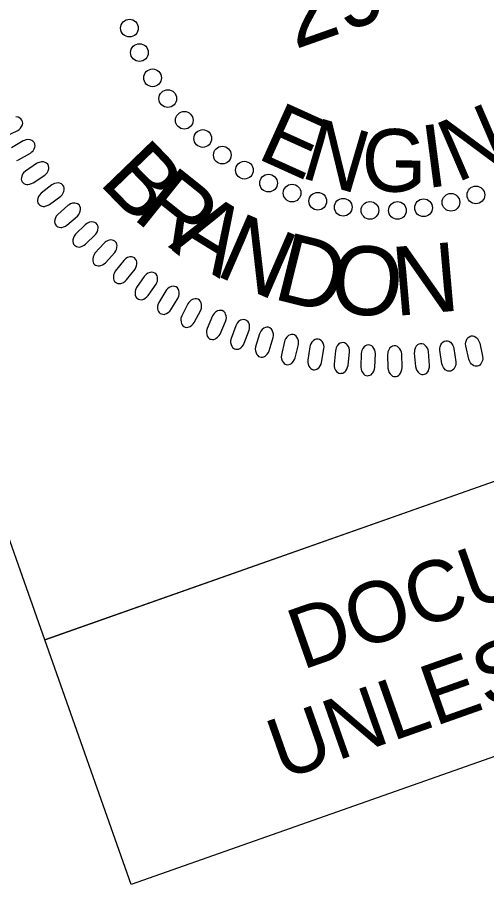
# Model space of a CAD drawing. Extents: x 473817 to 475769, y 501102 to 502694.
# Drawn here: x 475255.4 to 475297.9, y 502437.1 to 502515.6 of the extents above; entities that cross this region are included whole.
import ezdxf

# ---------------------------------------------------------------- set-up
doc = ezdxf.new("R2010")
doc.units = 0
for name, color, linetype in [('Sheet PE Seal Cell', 7, 'Continuous'), ('Sheet Plan CELL', 7, 'Continuous'), ('Sheet Sticker Exception Certification CELL', 7, 'Continuous')]:
    doc.layers.add(name, color=color, linetype=linetype)

msp = doc.modelspace()

# ---------------------------------------------------------------- linework, layer by layer
at = {"layer": 'Sheet PE Seal Cell'}
for points in [[(475254.29, 502504.832), (475255.418, 502505.388), (475255.559, 502505.484), (475255.664, 502505.587), (475255.766, 502505.738), (475255.841, 502505.9), (475255.869, 502506.023), (475255.852, 502506.191), (475255.803, 502506.333), (475255.7, 502506.449), (475255.609, 502506.52), (475255.463, 502506.59), (475255.258, 502506.62)], [(475255.337, 502502.659), (475255.485, 502502.72), (475256.575, 502503.346), (475256.71, 502503.451), (475256.809, 502503.56), (475256.901, 502503.717), (475256.966, 502503.885), (475256.986, 502504.009), (475256.958, 502504.174), (475256.9, 502504.314), (475256.791, 502504.423), (475256.695, 502504.488), (475256.545, 502504.548), (475256.338, 502504.566), (475256.149, 502504.533), (475256.022, 502504.494), (475255.903, 502504.442), (475254.843, 502503.825)]]:
    msp.add_lwpolyline(points, dxfattribs=at)
for points in [[(475257.134, 502502.393), (475256.114, 502501.711), (475255.953, 502501.558), (475255.865, 502501.437), (475255.787, 502501.249), (475255.75, 502501.107), (475255.746, 502500.97), (475255.771, 502500.861), (475255.817, 502500.756), (475255.896, 502500.675), (475255.987, 502500.592), (475256.095, 502500.538), (475256.237, 502500.507), (475256.336, 502500.501), (475256.498, 502500.528), (475256.68, 502500.579), (475256.825, 502500.649), (475257.874, 502501.341), (475258.002, 502501.455), (475258.093, 502501.57), (475258.176, 502501.733), (475258.229, 502501.904), (475258.241, 502502.028), (475258.204, 502502.193), (475258.137, 502502.328), (475258.021, 502502.43), (475257.921, 502502.489), (475257.768, 502502.54), (475257.561, 502502.544), (475257.373, 502502.501), (475257.249, 502502.453)], [(475258.51, 502500.457), (475257.535, 502499.712), (475257.384, 502499.549), (475257.304, 502499.423), (475257.238, 502499.23), (475257.21, 502499.086), (475257.214, 502498.949), (475257.246, 502498.842), (475257.298, 502498.741), (475257.382, 502498.664), (475257.479, 502498.587), (475257.59, 502498.54), (475257.733, 502498.518), (475257.832, 502498.518), (475257.992, 502498.556), (475258.171, 502498.618), (475258.312, 502498.697), (475259.314, 502499.454), (475259.435, 502499.575), (475259.519, 502499.695), (475259.591, 502499.863), (475259.634, 502500.037), (475259.638, 502500.163), (475259.59, 502500.324), (475259.515, 502500.455), (475259.393, 502500.549), (475259.29, 502500.602), (475259.134, 502500.642), (475258.926, 502500.634), (475258.743, 502500.579), (475258.622, 502500.524)], [(475259.969, 502498.599), (475259.043, 502497.795), (475258.902, 502497.622), (475258.831, 502497.491), (475258.777, 502497.295), (475258.758, 502497.15), (475258.771, 502497.013), (475258.809, 502496.908), (475258.868, 502496.81), (475258.956, 502496.739), (475259.058, 502496.668), (475259.171, 502496.628), (475259.315, 502496.615), (475259.415, 502496.622), (475259.572, 502496.67), (475259.746, 502496.742), (475259.882, 502496.83), (475260.835, 502497.648), (475260.949, 502497.777), (475261.024, 502497.902), (475261.086, 502498.074), (475261.117, 502498.251), (475261.114, 502498.377), (475261.056, 502498.535), (475260.973, 502498.661), (475260.845, 502498.747), (475260.738, 502498.793), (475260.58, 502498.824), (475260.374, 502498.802), (475260.194, 502498.736), (475260.077, 502498.673)], [(475261.536, 502496.862), (475260.662, 502496.001), (475260.532, 502495.82), (475260.469, 502495.685), (475260.428, 502495.486), (475260.418, 502495.339), (475260.44, 502495.203), (475260.485, 502495.101), (475260.549, 502495.007), (475260.642, 502494.942), (475260.748, 502494.877), (475260.864, 502494.845), (475261.008, 502494.841), (475261.107, 502494.854), (475261.261, 502494.911), (475261.43, 502494.995), (475261.56, 502495.09), (475262.46, 502495.967), (475262.565, 502496.103), (475262.633, 502496.232), (475262.683, 502496.408), (475262.704, 502496.586), (475262.693, 502496.712), (475262.625, 502496.866), (475262.534, 502496.986), (475262.401, 502497.064), (475262.291, 502497.104), (475262.131, 502497.125), (475261.927, 502497.09), (475261.751, 502497.012), (475261.638, 502496.942)], [(475263.238, 502495.184), (475262.42, 502494.269), (475262.302, 502494.081), (475262.248, 502493.942), (475262.218, 502493.741), (475262.218, 502493.594), (475262.248, 502493.46), (475262.299, 502493.36), (475262.37, 502493.271), (475262.467, 502493.212), (475262.576, 502493.154), (475262.694, 502493.129), (475262.838, 502493.133), (475262.936, 502493.153), (475263.086, 502493.22), (475263.25, 502493.314), (475263.373, 502493.417), (475264.216, 502494.349), (475264.313, 502494.491), (475264.372, 502494.625), (475264.411, 502494.803), (475264.421, 502494.982), (475264.402, 502495.107), (475264.324, 502495.255), (475264.226, 502495.37), (475264.088, 502495.44), (475263.977, 502495.473), (475263.816, 502495.483), (475263.614, 502495.436), (475263.444, 502495.347), (475263.335, 502495.271)], [(475265.018, 502493.612), (475264.26, 502492.647), (475264.153, 502492.452), (475264.108, 502492.31), (475264.091, 502492.107), (475264.1, 502491.961), (475264.139, 502491.829), (475264.196, 502491.733), (475264.272, 502491.648), (475264.373, 502491.595), (475264.485, 502491.544), (475264.604, 502491.526), (475264.748, 502491.54), (475264.844, 502491.566), (475264.99, 502491.642), (475265.148, 502491.746), (475265.264, 502491.857), (475266.047, 502492.84), (475266.134, 502492.987), (475266.185, 502493.126), (475266.213, 502493.306), (475266.212, 502493.485), (475266.185, 502493.608), (475266.098, 502493.752), (475265.993, 502493.86), (475265.851, 502493.921), (475265.738, 502493.946), (475265.576, 502493.947), (475265.378, 502493.887), (475265.213, 502493.787), (475265.11, 502493.704)], [(475266.879, 502492.174), (475266.182, 502491.163), (475266.089, 502490.962), (475266.051, 502490.817), (475266.048, 502490.614), (475266.066, 502490.469), (475266.113, 502490.339), (475266.176, 502490.247), (475266.258, 502490.166), (475266.361, 502490.12), (475266.477, 502490.076), (475266.597, 502490.066), (475266.739, 502490.089), (475266.834, 502490.121), (475266.974, 502490.206), (475267.125, 502490.319), (475267.235, 502490.438), (475267.954, 502491.468), (475268.032, 502491.621), (475268.074, 502491.761), (475268.091, 502491.943), (475268.078, 502492.121), (475268.044, 502492.243), (475267.948, 502492.381), (475267.836, 502492.482), (475267.69, 502492.534), (475267.576, 502492.553), (475267.415, 502492.543), (475267.22, 502492.471), (475267.063, 502492.361), (475266.965, 502492.272)], [(475268.828, 502490.866), (475268.196, 502489.814), (475268.116, 502489.608), (475268.088, 502489.461), (475268.097, 502489.258), (475268.124, 502489.113), (475268.179, 502488.988), (475268.248, 502488.899), (475268.334, 502488.825), (475268.44, 502488.784), (475268.558, 502488.748), (475268.679, 502488.745), (475268.819, 502488.777), (475268.912, 502488.815), (475269.047, 502488.908), (475269.19, 502489.031), (475269.292, 502489.156), (475269.946, 502490.23), (475270.014, 502490.386), (475270.047, 502490.53), (475270.052, 502490.712), (475270.028, 502490.89), (475269.986, 502491.008), (475269.882, 502491.141), (475269.764, 502491.234), (475269.616, 502491.277), (475269.5, 502491.288), (475269.34, 502491.268), (475269.15, 502491.185), (475268.999, 502491.065), (475268.907, 502490.97)], [(475270.841, 502489.699), (475270.276, 502488.609), (475270.209, 502488.398), (475270.191, 502488.25), (475270.212, 502488.047), (475270.248, 502487.905), (475270.311, 502487.783), (475270.386, 502487.699), (475270.476, 502487.63), (475270.585, 502487.596), (475270.705, 502487.568), (475270.825, 502487.572), (475270.964, 502487.613), (475271.053, 502487.656), (475271.183, 502487.758), (475271.318, 502487.89), (475271.412, 502488.021), (475271.996, 502489.133), (475272.055, 502489.294), (475272.078, 502489.439), (475272.073, 502489.622), (475272.038, 502489.797), (475271.988, 502489.913), (475271.876, 502490.039), (475271.752, 502490.125), (475271.601, 502490.158), (475271.485, 502490.162), (475271.326, 502490.132), (475271.143, 502490.037), (475271, 502489.908), (475270.914, 502489.806)], [(475273.069, 502488.599), (475272.574, 502487.476), (475272.52, 502487.26), (475272.511, 502487.111), (475272.545, 502486.911), (475272.59, 502486.771), (475272.66, 502486.653), (475272.74, 502486.575), (475272.835, 502486.511), (475272.945, 502486.484), (475273.067, 502486.463), (475273.187, 502486.475), (475273.323, 502486.525), (475273.409, 502486.573), (475273.532, 502486.683), (475273.658, 502486.823), (475273.744, 502486.96), (475274.257, 502488.107), (475274.305, 502488.271), (475274.32, 502488.417), (475274.303, 502488.599), (475274.257, 502488.772), (475274.2, 502488.884), (475274.081, 502489.003), (475273.951, 502489.081), (475273.799, 502489.105), (475273.683, 502489.101), (475273.526, 502489.062), (475273.349, 502488.955), (475273.214, 502488.817), (475273.135, 502488.711)], [(475275.172, 502487.718), (475274.748, 502486.566), (475274.708, 502486.347), (475274.708, 502486.198), (475274.755, 502486), (475274.809, 502485.864), (475274.886, 502485.75), (475274.97, 502485.676), (475275.069, 502485.618), (475275.18, 502485.599), (475275.303, 502485.586), (475275.422, 502485.606), (475275.555, 502485.664), (475275.639, 502485.717), (475275.754, 502485.835), (475275.872, 502485.982), (475275.948, 502486.125), (475276.388, 502487.301), (475276.426, 502487.468), (475276.431, 502487.615), (475276.403, 502487.795), (475276.346, 502487.965), (475276.282, 502488.074), (475276.155, 502488.184), (475276.022, 502488.254), (475275.868, 502488.268), (475275.752, 502488.258), (475275.599, 502488.208), (475275.428, 502488.09), (475275.302, 502487.945), (475275.23, 502487.834)], [(475277.317, 502486.989), (475276.967, 502485.813), (475276.94, 502485.592), (475276.95, 502485.443), (475277.009, 502485.248), (475277.071, 502485.116), (475277.156, 502485.007), (475277.244, 502484.939), (475277.346, 502484.888), (475277.459, 502484.875), (475277.583, 502484.87), (475277.7, 502484.897), (475277.829, 502484.963), (475277.909, 502485.022), (475278.016, 502485.147), (475278.124, 502485.301), (475278.192, 502485.448), (475278.558, 502486.65), (475278.585, 502486.819), (475278.581, 502486.966), (475278.541, 502487.144), (475278.474, 502487.31), (475278.403, 502487.414), (475278.27, 502487.517), (475278.132, 502487.578), (475277.977, 502487.582), (475277.863, 502487.564), (475277.713, 502487.506), (475277.55, 502487.377), (475277.434, 502487.224), (475277.368, 502487.108)], [(475279.581, 502486.289), (475279.305, 502485.093), (475279.292, 502484.871), (475279.311, 502484.723), (475279.382, 502484.532), (475279.452, 502484.404), (475279.544, 502484.301), (475279.636, 502484.238), (475279.742, 502484.194), (475279.855, 502484.188), (475279.979, 502484.19), (475280.094, 502484.225), (475280.218, 502484.299), (475280.295, 502484.363), (475280.394, 502484.493), (475280.492, 502484.655), (475280.55, 502484.805), (475280.84, 502486.028), (475280.856, 502486.199), (475280.843, 502486.344), (475280.792, 502486.52), (475280.715, 502486.682), (475280.637, 502486.781), (475280.498, 502486.875), (475280.357, 502486.928), (475280.202, 502486.922), (475280.089, 502486.897), (475279.943, 502486.829), (475279.788, 502486.691), (475279.682, 502486.531), (475279.624, 502486.411)], [(475297.27, 502486.144), (475297.529, 502484.944), (475297.539, 502484.722), (475297.517, 502484.574), (475297.444, 502484.385), (475297.372, 502484.257), (475297.279, 502484.155), (475297.185, 502484.095), (475297.08, 502484.052), (475296.967, 502484.048), (475296.843, 502484.051), (475296.728, 502484.087), (475296.605, 502484.163), (475296.529, 502484.228), (475296.432, 502484.361), (475296.336, 502484.523), (475296.28, 502484.674), (475296.007, 502485.9), (475295.993, 502486.071), (475296.008, 502486.217), (475296.061, 502486.392), (475296.141, 502486.552), (475296.22, 502486.651), (475296.36, 502486.743), (475296.502, 502486.793), (475296.657, 502486.786), (475296.77, 502486.76), (475296.915, 502486.689), (475297.067, 502486.549), (475297.171, 502486.387), (475297.228, 502486.267)], [(475281.888, 502485.813), (475281.687, 502484.603), (475281.689, 502484.38), (475281.717, 502484.234), (475281.8, 502484.048), (475281.878, 502483.924), (475281.976, 502483.827), (475282.072, 502483.771), (475282.18, 502483.733), (475282.293, 502483.734), (475282.416, 502483.744), (475282.53, 502483.786), (475282.649, 502483.868), (475282.721, 502483.936), (475282.812, 502484.073), (475282.9, 502484.24), (475282.949, 502484.394), (475283.161, 502485.633), (475283.166, 502485.803), (475283.145, 502485.949), (475283.082, 502486.121), (475282.995, 502486.277), (475282.912, 502486.371), (475282.767, 502486.456), (475282.622, 502486.5), (475282.469, 502486.485), (475282.357, 502486.453), (475282.215, 502486.376), (475282.07, 502486.227), (475281.974, 502486.061), (475281.923, 502485.939)], [(475284.198, 502485.454), (475284.074, 502484.234), (475284.089, 502484.012), (475284.127, 502483.868), (475284.221, 502483.687), (475284.307, 502483.569), (475284.41, 502483.478), (475284.51, 502483.428), (475284.621, 502483.397), (475284.734, 502483.406), (475284.856, 502483.423), (475284.966, 502483.472), (475285.08, 502483.561), (475285.148, 502483.634), (475285.23, 502483.776), (475285.308, 502483.948), (475285.346, 502484.105), (475285.48, 502485.354), (475285.475, 502485.526), (475285.444, 502485.669), (475285.372, 502485.837), (475285.274, 502485.987), (475285.185, 502486.076), (475285.035, 502486.151), (475284.888, 502486.186), (475284.736, 502486.162), (475284.626, 502486.123), (475284.49, 502486.037), (475284.354, 502485.88), (475284.269, 502485.707), (475284.226, 502485.582)], [(475291.347, 502485.236), (475291.453, 502484.014), (475291.51, 502483.799), (475291.574, 502483.664), (475291.701, 502483.505), (475291.807, 502483.404), (475291.926, 502483.335), (475292.033, 502483.303), (475292.147, 502483.294), (475292.256, 502483.324), (475292.373, 502483.364), (475292.472, 502483.432), (475292.568, 502483.541), (475292.621, 502483.625), (475292.674, 502483.78), (475292.718, 502483.965), (475292.726, 502484.126), (475292.625, 502485.378), (475292.587, 502485.545), (475292.53, 502485.68), (475292.427, 502485.831), (475292.303, 502485.96), (475292.199, 502486.031), (475292.038, 502486.077), (475291.887, 502486.084), (475291.741, 502486.031), (475291.642, 502485.972), (475291.524, 502485.862), (475291.42, 502485.683), (475291.368, 502485.498), (475291.35, 502485.366)], [(475294.93, 502485.664), (475295.113, 502484.451), (475295.109, 502484.229), (475295.079, 502484.083), (475294.993, 502483.898), (475294.913, 502483.776), (475294.814, 502483.68), (475294.717, 502483.625), (475294.609, 502483.589), (475294.496, 502483.591), (475294.373, 502483.603), (475294.26, 502483.646), (475294.142, 502483.729), (475294.071, 502483.799), (475293.982, 502483.937), (475293.896, 502484.106), (475293.85, 502484.26), (475293.655, 502485.501), (475293.651, 502485.673), (475293.675, 502485.817), (475293.739, 502485.988), (475293.829, 502486.143), (475293.914, 502486.237), (475294.059, 502486.319), (475294.205, 502486.361), (475294.358, 502486.344), (475294.47, 502486.31), (475294.61, 502486.232), (475294.753, 502486.081), (475294.847, 502485.914), (475294.895, 502485.791)], [(475286.54, 502485.211), (475286.493, 502483.985), (475286.521, 502483.764), (475286.568, 502483.623), (475286.674, 502483.449), (475286.767, 502483.336), (475286.876, 502483.252), (475286.979, 502483.208), (475287.091, 502483.184), (475287.203, 502483.199), (475287.324, 502483.225), (475287.431, 502483.28), (475287.539, 502483.376), (475287.602, 502483.454), (475287.674, 502483.6), (475287.741, 502483.777), (475287.77, 502483.936), (475287.825, 502485.192), (475287.81, 502485.362), (475287.769, 502485.503), (475287.687, 502485.666), (475287.58, 502485.81), (475287.485, 502485.893), (475287.331, 502485.959), (475287.182, 502485.985), (475287.032, 502485.95), (475286.925, 502485.904), (475286.794, 502485.81), (475286.668, 502485.645), (475286.594, 502485.468), (475286.56, 502485.34)], [(475288.923, 502485.095), (475288.953, 502483.868), (475288.995, 502483.65), (475289.051, 502483.512), (475289.167, 502483.345), (475289.267, 502483.237), (475289.382, 502483.161), (475289.486, 502483.123), (475289.599, 502483.106), (475289.711, 502483.129), (475289.83, 502483.162), (475289.933, 502483.224), (475290.035, 502483.327), (475290.093, 502483.408), (475290.157, 502483.559), (475290.212, 502483.74), (475290.231, 502483.9), (475290.207, 502485.156), (475290.18, 502485.325), (475290.132, 502485.464), (475290.039, 502485.621), (475289.923, 502485.758), (475289.824, 502485.835), (475289.666, 502485.891), (475289.516, 502485.907), (475289.367, 502485.864), (475289.264, 502485.811), (475289.139, 502485.709), (475289.024, 502485.537), (475288.961, 502485.355), (475288.935, 502485.225)]]:
    msp.add_lwpolyline(points, close=True, dxfattribs=at)
for centre in [(475265.543, 502514.657), (475266.45, 502512.443), (475267.635, 502510.157), (475269.014, 502508.278), (475270.509, 502506.312), (475272.186, 502504.665), (475273.955, 502503.163), (475275.956, 502501.798), (475278.142, 502500.626), (475280.273, 502499.729), (475296.923, 502499.554), (475282.602, 502498.987), (475294.668, 502498.886), (475284.903, 502498.446), (475287.326, 502498.159), (475289.82, 502498.15), (475292.183, 502498.391)]:
    msp.add_circle(centre, 0.801, dxfattribs=at)
at = {"layer": 'Sheet Plan CELL'}
msp.add_lwpolyline([(475220.449, 502565.356), (475314.805, 502598.626), (475352.22, 502492.517), (475257.868, 502459.274)], close=True, dxfattribs=at)
at = {"layer": 'Sheet Sticker Exception Certification CELL'}
for p, q in [((475257.868, 502459.274), (475446.521, 502525.794)), ((475257.868, 502459.274), (475446.521, 502525.794)), ((475454.335, 502503.632), (475265.682, 502437.111)), ((475454.335, 502503.632), (475265.682, 502437.111)), ((475265.682, 502437.111), (475257.868, 502459.274)), ((475265.682, 502437.111), (475257.868, 502459.274))]:
    msp.add_line(p, q, dxfattribs=at)

# ---------------------------------------------------------------- texts
at = {"layer": 'Sheet PE Seal Cell'}
for s, height, rotation, p in [('29470', 6.2363, 19.40435, (475280.535, 502512.72)), ('E', 5.669, 335.68858, (475276.963, 502502.915)), ('N', 5.669, 23.32736, (475295.172, 502500.624)), ('N', 5.669, 343.62837, (475280.902, 502501.17)), ('I', 5.669, 7.44777, (475292.418, 502500.154)), ('G', 5.669, 359.50797, (475286.548, 502499.876)), ('B', 6.236, 314.01269, (475262.661, 502500.652)), ('R', 6.236, 321.28772, (475265.685, 502497.523)), ('A', 6.236, 328.40456, (475269.003, 502494.856)), ('N', 6.236, 336.51573, (475273.154, 502492.345)), ('D', 6.236, 346.00542, (475278.4, 502490.186)), ('O', 6.236, 354.87365, (475283.562, 502488.976)), ('N', 6.236, 4.9735, (475289.587, 502488.585))]:
    msp.add_text(s, height=height, rotation=rotation, dxfattribs=at).set_placement(p)
at = {"layer": 'Sheet Sticker Exception Certification CELL'}
for s, p in [('DOCUMENT NOT CONSIDERED FINAL', (475281.18, 502456.524)), ('DOCUMENT NOT CONSIDERED FINAL', (475281.18, 502456.524)), ('UNLESS ALL SIGNATURES COMPLETED', (475279.323, 502446.539)), ('UNLESS ALL SIGNATURES COMPLETED', (475279.323, 502446.539))]:
    msp.add_text(s, height=5.5, rotation=19.42299, dxfattribs=at).set_placement(p)

doc.saveas('drawing.dxf')
